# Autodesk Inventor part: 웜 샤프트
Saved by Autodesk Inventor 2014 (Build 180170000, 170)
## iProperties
Created: 2026-07
Part Number: 웜 샤프트
Material: 강철, 합금
Document SubType Name: Modeling
Designer: dg
Density: 7.85 g/cm^3
Appearance: 반연마
Mass: 385.751 g
Surface Area: 140.519 cm^2
Volume: 49.1403 cm^3
Author: jhkim
Creation Date: 2026-07-02
Sending System: Autodesk Inventor 2027
Preprocessor: ST-DEVELOPER v20.1
Author: dg
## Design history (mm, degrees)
node "웜 샤프트1"
node "솔리드1"
node "기준1"
